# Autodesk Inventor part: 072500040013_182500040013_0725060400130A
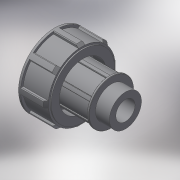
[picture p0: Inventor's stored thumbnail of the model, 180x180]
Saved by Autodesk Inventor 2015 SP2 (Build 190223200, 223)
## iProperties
Created: 2017-04
Part Number: 072500040013_182500040013_0725060400130A
Material: Generic
Description: PLASSON THREADED ADAPTOR 40-1.1/4"
Document SubType Name: Modeling
Designer: KIM
Density: 1 g/cm^3
Appearance: Default
Author: KIM
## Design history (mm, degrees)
derived "07250.ipt"
feature "Solid1::07250.ipt"
tag "TaggingFeature1"
body "Solid1"
other parameters: "d1" = 41.91, "d3" = 22, "d6" = 82, "d7" = 76.26, "d8" = 65.6, "d10" = 50.292, "d12" = 25.146, "d13" = 33.528, "d14" = 25.3, "d15" = 61.5, "d16" = 3, "d18" = 22, "d19" = 26.4, "d24" = 8.382, "d25" = 4.191, "d27" = 0, "d28" = 3.3528, "d31" = 0.8382, "d35" = 360 deg, "d41" = 29.337, "d56" = 44, "d57" = 4, "d58" = 2, "d60" = 0, "d61" = 0.4191, "d64" = 0.4191, "d68" = 360 deg, "R_" = 41.91, "E_" = 82, "l_2" = 22
